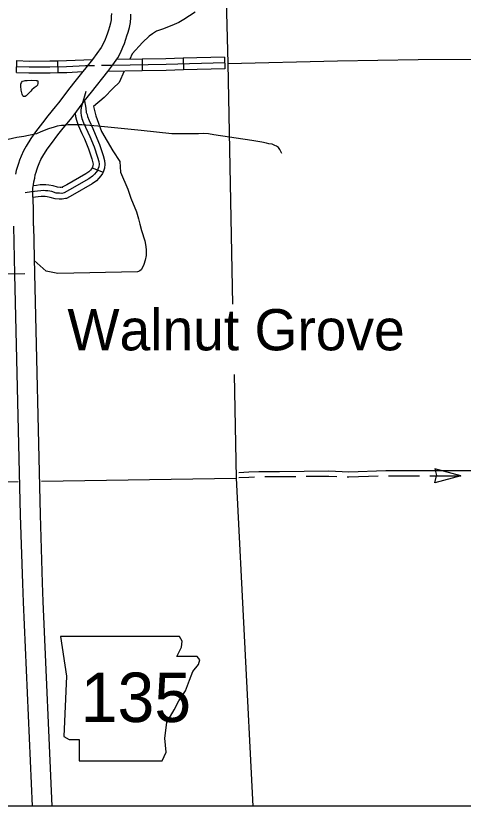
# Model space of a CAD drawing. Extents: x 1164457 to 1439835, y 1590918 to 1773502.
# Drawn here: x 1317083 to 1322808, y 1614471 to 1624593 of the extents above; entities that cross this region are included whole.
import ezdxf

# ---------------------------------------------------------------- set-up
doc = ezdxf.new("R2010")
doc.units = 0
for name, color, linetype in [('Level 10', 7, 'Continuous'), ('Level 21', 7, 'Continuous'), ('Level 24', 7, 'Continuous'), ('Level 29', 7, 'Continuous'), ('Level 31', 7, 'Continuous'), ('Level 32', 7, 'Continuous'), ('Level 35', 7, 'Continuous'), ('Level 43', 7, 'Continuous'), ('Level 45', 7, 'Continuous'), ('Level 5', 7, 'Continuous'), ('R_Draft', 7, 'Continuous')]:
    doc.layers.add(name, color=color, linetype=linetype)

msp = doc.modelspace()

# ---------------------------------------------------------------- linework, layer by layer
at = {"layer": 'Level 10'}
for points in [[(1318306, 1624623), (1318305, 1624586), (1318302, 1624541), (1318294, 1624500), (1318281, 1624454), (1318268, 1624411), (1318255, 1624371), (1318240, 1624325), (1318225, 1624290), (1318201, 1624234), (1318174, 1624189), (1318122, 1624110), (1318066, 1624036), (1317854, 1623772), (1317759, 1623650), (1317698, 1623568), (1317631, 1623478), (1317589, 1623426), (1317494, 1623311), (1317425, 1623224), (1317337, 1623109), (1317277, 1623024), (1317215, 1622925), (1317181, 1622864), (1317150, 1622794), (1317131, 1622745), (1317116, 1622702), (1317104, 1622664), (1317089, 1622612), (1317081, 1622566)], [(1317309, 1621902), (1317308, 1622132), (1317302, 1622313), (1317303, 1622387), (1317309, 1622427), (1317315, 1622469), (1317326, 1622515), (1317333, 1622555), (1317344, 1622593), (1317353, 1622622), (1317366, 1622658), (1317381, 1622700), (1317404, 1622752), (1317430, 1622797), (1317485, 1622884), (1317539, 1622960), (1317623, 1623071), (1317688, 1623154), (1317782, 1623267), (1317829, 1623324), (1317898, 1623419), (1317958, 1623499), (1318050, 1623617), (1318262, 1623882), (1318326, 1623965), (1318387, 1624057), (1318424, 1624120), (1318455, 1624191), (1318475, 1624238), (1318493, 1624295), (1318506, 1624336), (1318521, 1624383), (1318538, 1624443), (1318550, 1624509), (1318555, 1624573), (1318556, 1624614)], [(1317295, 1614471), (1317181, 1617082), (1317172, 1617323), (1317145, 1618196), (1317072, 1621286), (1317059, 1621898)], [(1317309, 1621904), (1317322, 1621292), (1317395, 1618203), (1317422, 1617331), (1317431, 1617092), (1317545, 1614471)]]:
    msp.add_lwpolyline(points, dxfattribs=at)
at = {"layer": 'Level 21'}
msp.add_lwpolyline([(1317655, 1616643), (1317731, 1616135), (1317697, 1615365), (1317765, 1615323), (1317892, 1615323), (1317892, 1615052), (1318958, 1615052), (1319008, 1615162), (1318992, 1615340), (1319017, 1615543), (1319110, 1615704), (1319169, 1615822), (1319254, 1615949), (1319305, 1616084), (1319347, 1616194), (1319423, 1616287), (1319440, 1616347), (1319406, 1616389), (1319144, 1616389), (1319203, 1616507), (1319212, 1616583), (1319176, 1616642)], close=True, dxfattribs=at)
at = {"layer": 'Level 29'}
for points in [[(1319080, 1623083), (1318686, 1623125), (1318132, 1623179), (1317929, 1623196), (1317876, 1623198), (1317752, 1623195), (1317702, 1623189), (1317670, 1623188), (1317614, 1623181), (1317576, 1623169), (1317502, 1623147), (1317405, 1623106), (1317347, 1623083), (1317247, 1623061), (1317188, 1623049), (1317097, 1623035), (1316987, 1623011)], [(1320488, 1622832), (1320463, 1622883), (1320445, 1622905), (1320419, 1622925), (1320399, 1622934), (1320362, 1622948), (1320323, 1622955), (1320293, 1622962), (1320232, 1622974), (1320104, 1622996), (1319619, 1623071), (1319550, 1623080), (1319484, 1623085), (1319422, 1623082), (1319391, 1623083), (1319276, 1623083), (1319080, 1623083)]]:
    msp.add_lwpolyline(points, dxfattribs=at)
at = {"layer": 'Level 31'}
msp.add_lwpolyline([(1317197, 1621289), (1315230, 1621264)], dxfattribs=at)
at = {"layer": 'Level 32'}
for p, q in [((1317093, 1623869), (1317098, 1624019)), ((1317624, 1623867), (1317622, 1624017)), ((1318700, 1624039), (1318702, 1623889)), ((1319227, 1624050), (1319231, 1623900)), ((1319755, 1624065), (1319759, 1623915))]:
    msp.add_line(p, q, dxfattribs=at)
for points in [[(1317098, 1624019), (1317254, 1624014), (1317519, 1624015), (1317622, 1624017)], [(1317622, 1624017), (1317732, 1624019), (1318065, 1624036)], [(1319757, 1623990), (1319007, 1623969), (1318315, 1623958), (1318182, 1623959)], [(1318700, 1624039), (1318373, 1624034)], [(1319227, 1624050), (1319005, 1624044), (1318700, 1624039)], [(1319755, 1624065), (1319227, 1624050)], [(1317095, 1623944), (1317253, 1623939), (1317520, 1623940), (1317734, 1623944), (1317973, 1623956), (1318091, 1623958)], [(1317624, 1623867), (1317737, 1623869), (1317940, 1623879)], [(1318702, 1623889), (1318262, 1623882)], [(1319231, 1623900), (1319008, 1623894), (1318702, 1623889)], [(1319759, 1623915), (1319231, 1623900)], [(1317093, 1623869), (1317252, 1623864), (1317521, 1623865), (1317624, 1623867)]]:
    msp.add_lwpolyline(points, dxfattribs=at)
at = {"layer": 'Level 35'}
for points in [[(1319378, 1624640), (1319234, 1624546), (1319170, 1624508), (1319082, 1624469), (1318962, 1624423), (1318883, 1624395), (1318832, 1624364), (1318788, 1624331), (1318703, 1624253), (1318573, 1624105), (1318541, 1624037)], [(1318471, 1623886), (1318404, 1623739), (1318331, 1623666), (1318212, 1623547), (1318077, 1623430), (1318106, 1623311), (1318182, 1623110), (1318326, 1622866), (1318415, 1622727)], [(1317276, 1623630), (1317245, 1623599), (1317216, 1623568), (1317203, 1623559), (1317195, 1623558), (1317182, 1623559), (1317174, 1623567), (1317164, 1623592), (1317152, 1623641), (1317146, 1623693), (1317146, 1623719), (1317154, 1623740), (1317171, 1623755), (1317189, 1623760), (1317203, 1623763), (1317230, 1623766)], [(1317230, 1623766), (1317287, 1623769), (1317343, 1623766), (1317361, 1623764), (1317366, 1623753), (1317366, 1623748), (1317366, 1623730), (1317360, 1623704), (1317345, 1623690), (1317317, 1623672), (1317287, 1623644), (1317276, 1623630)], [(1318415, 1622727), (1318425, 1622589), (1318516, 1622375), (1318556, 1622259), (1318628, 1622081), (1318652, 1621992), (1318669, 1621924), (1318692, 1621845), (1318736, 1621710), (1318747, 1621638), (1318751, 1621591), (1318750, 1621525), (1318739, 1621463), (1318722, 1621409), (1318705, 1621372), (1318688, 1621342), (1318672, 1621328), (1318653, 1621317), (1318640, 1621313), (1317621, 1621294), (1317472, 1621324), (1317319, 1621459)]]:
    msp.add_lwpolyline(points, dxfattribs=at)
at = {"layer": 'Level 43'}
for p, q in [((1322777, 1618703), (1322445, 1618792)), ((1322445, 1618792), (1322469, 1618704)), ((1322777, 1618703), (1322445, 1618614)), ((1322445, 1618614), (1322469, 1618703))]:
    msp.add_line(p, q, dxfattribs=at)
for points in [[(1319939, 1618746), (1320065, 1618751), (1320194, 1618756), (1320458, 1618759), (1321089, 1618764), (1321346, 1618755), (1321817, 1618769), (1323961, 1618768), (1324024, 1618771), (1324392, 1618774), (1324529, 1618772), (1324797, 1618777)], [(1319939, 1618681), (1320065, 1618686), (1320137, 1618689)], [(1320269, 1618692), (1320458, 1618693), (1320665, 1618695)], [(1320797, 1618696), (1321089, 1618698), (1321193, 1618695)], [(1321325, 1618691), (1321346, 1618690), (1321721, 1618701)], [(1321853, 1618703), (1322249, 1618703)], [(1322381, 1618703), (1322777, 1618703)]]:
    msp.add_lwpolyline(points, dxfattribs=at)
at = {"layer": 'Level 45'}
msp.add_line((1318062, 1622648), (1318200, 1622591), dxfattribs=at)
for points in [[(1317978, 1623622), (1317931, 1623463), (1317919, 1623418), (1317916, 1623379), (1317916, 1623352), (1317921, 1623315), (1317930, 1623280), (1317951, 1623223), (1318030, 1623049), (1318084, 1622917), (1318128, 1622784), (1318144, 1622727), (1318148, 1622695), (1318144, 1622660), (1318135, 1622630), (1318127, 1622611), (1318113, 1622590), (1318092, 1622565), (1318066, 1622539), (1318018, 1622505), (1317772, 1622363), (1317703, 1622326), (1317671, 1622319), (1317643, 1622321), (1317601, 1622324), (1317543, 1622342), (1317495, 1622350), (1317464, 1622353), (1317433, 1622355), (1317403, 1622353), (1317359, 1622348), (1317284, 1622339), (1317204, 1622325)], [(1317963, 1623506), (1317979, 1623409), (1317985, 1623356), (1317995, 1623329), (1318001, 1623302), (1318020, 1623251), (1318067, 1623150)], [(1317842, 1623342), (1317847, 1623302), (1317858, 1623258), (1317881, 1623194), (1317930, 1623087)], [(1317930, 1623087), (1317962, 1623019), (1318014, 1622891), (1318057, 1622763), (1318070, 1622712), (1318073, 1622694), (1318070, 1622675), (1318064, 1622655), (1318062, 1622648)], [(1318067, 1623150), (1318099, 1623078), (1318155, 1622944), (1318200, 1622806), (1318218, 1622742), (1318224, 1622695), (1318218, 1622644), (1318206, 1622605), (1318200, 1622591)], [(1318062, 1622648), (1318061, 1622647), (1318053, 1622635), (1318037, 1622616), (1318018, 1622597), (1317978, 1622568), (1317735, 1622429), (1317677, 1622397), (1317684, 1622398)], [(1318200, 1622591), (1318194, 1622575), (1318173, 1622545), (1318147, 1622514), (1318114, 1622482), (1318059, 1622442), (1317808, 1622298), (1317730, 1622255), (1317718, 1622252)], [(1317684, 1622398), (1317665, 1622394), (1317649, 1622395), (1317615, 1622398), (1317560, 1622415), (1317505, 1622425), (1317469, 1622428), (1317433, 1622430), (1317396, 1622428), (1317350, 1622422), (1317307, 1622417)], [(1317718, 1622252), (1317677, 1622243), (1317637, 1622246), (1317587, 1622250), (1317525, 1622268), (1317485, 1622276), (1317459, 1622278), (1317433, 1622280), (1317409, 1622278), (1317368, 1622273), (1317303, 1622266)]]:
    msp.add_lwpolyline(points, dxfattribs=at)
at = {"layer": 'Level 5'}
for points in [[(1319755, 1625618), (1319797, 1623981)], [(1319797, 1623981), (1321202, 1624016), (1322234, 1624033), (1325178, 1624053)], [(1319797, 1623981), (1319858, 1620902)], [(1319876, 1620001), (1319902, 1618674)], [(1314633, 1618592), (1317112, 1618631)], [(1317414, 1618635), (1319902, 1618674)], [(1319902, 1618674), (1320116, 1614471)]]:
    msp.add_lwpolyline(points, dxfattribs=at)
at = {"layer": 'R_Draft'}
msp.add_lwpolyline([(1246398, 1678582), (1349820, 1678582), (1349820, 1614471), (1246398, 1614471)], close=True, dxfattribs=at)

# ---------------------------------------------------------------- texts
at = {"layer": 'Level 21'}
msp.add_text('135', height=633, dxfattribs=at).set_placement((1317914, 1615549))
at = {"layer": 'Level 24'}
msp.add_text('Walnut Grove', height=528, dxfattribs=at).set_placement((1317744, 1620309))

doc.saveas('drawing.dxf')
